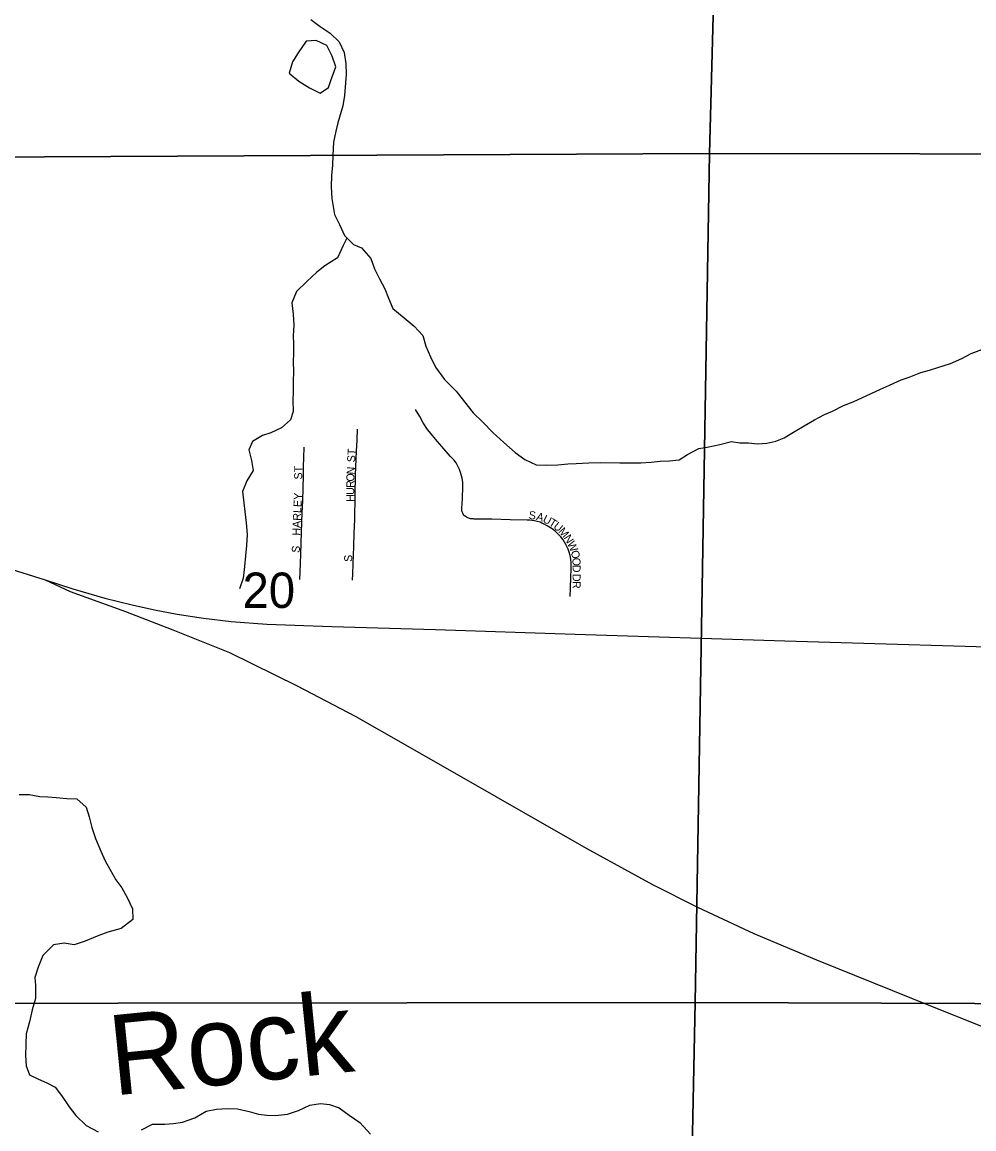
# Model space of a CAD drawing. Extents: x 1772825 to 1773716, y 1138558 to 1139032.
# Drawn here: x 1772828.624 to 1772829.187, y 1138562.068 to 1138562.723 of the extents above; entities that cross this region are included whole.
import ezdxf

# ---------------------------------------------------------------- set-up
doc = ezdxf.new("R2010")
doc.units = 0
for name, color, linetype in [('GM_X_Minor_Lake', 7, 'Continuous'), ('GM_X_Minor_River', 7, 'Continuous'), ('GM_X_Minor_River_Text', 7, 'Continuous'), ('GM_X_Rail_Line', 7, 'Continuous'), ('GM_X_Section', 7, 'Continuous'), ('GM_X_Section_Text', 7, 'Continuous'), ('GM_X_Township_Subdivision', 7, 'Continuous'), ('GM_X_Township_Subdivision_Text', 7, 'Continuous')]:
    doc.layers.add(name, color=color, linetype=linetype)

msp = doc.modelspace()

# ---------------------------------------------------------------- linework, layer by layer
at = {"layer": 'GM_X_Minor_Lake'}
for points in [[(1772828.80638, 1138562.6885), (1772828.8095, 1138562.6967), (1772828.80727, 1138562.70298), (1772828.80409, 1138562.70926), (1772828.79786, 1138562.71215), (1772828.79179, 1138562.7118), (1772828.78721, 1138562.705), (1772828.78376, 1138562.6997), (1772828.78183, 1138562.69288)], [(1772828.78183, 1138562.69288), (1772828.78748, 1138562.6881), (1772828.79389, 1138562.68427), (1772828.80013, 1138562.681), (1772828.80507, 1138562.68439), (1772828.80638, 1138562.6885)]]:
    msp.add_lwpolyline(points, dxfattribs=at)
at = {"layer": 'GM_X_Minor_River'}
for points in [[(1772828.79453, 1138562.7247), (1772828.80018, 1138562.72049), (1772828.80603, 1138562.71666), (1772828.81149, 1138562.7115), (1772828.81429, 1138562.70522), (1772828.81538, 1138562.69838), (1772828.81554, 1138562.69211), (1772828.81451, 1138562.67978), (1772828.81353, 1138562.6735)], [(1772828.81353, 1138562.6735), (1772828.81064, 1138562.66357), (1772828.80946, 1138562.65865), (1772828.80809, 1138562.65202), (1772828.80765, 1138562.64443), (1772828.80742, 1138562.63817), (1772828.80681, 1138562.63248), (1772828.80657, 1138562.62565), (1772828.80709, 1138562.61882), (1772828.80781, 1138562.61407), (1772828.80873, 1138562.60932), (1772828.81153, 1138562.60342), (1772828.81452, 1138562.59675), (1772828.81979, 1138562.59159), (1772828.82471, 1138562.58947), (1772828.83017, 1138562.58316), (1772828.8324, 1138562.57708), (1772828.8352, 1138562.57117), (1772828.83838, 1138562.56527), (1772828.84062, 1138562.55975), (1772828.84323, 1138562.55365), (1772828.84983, 1138562.5481), (1772828.85587, 1138562.54312), (1772828.86095, 1138562.53758), (1772828.8628, 1138562.53131), (1772828.86541, 1138562.52503), (1772828.86841, 1138562.51893), (1772828.87386, 1138562.51168), (1772828.88064, 1138562.5048), (1772828.88552, 1138562.4985), (1772828.89079, 1138562.49182), (1772828.89644, 1138562.48646), (1772828.90247, 1138562.48016), (1772828.90888, 1138562.47442), (1772828.91566, 1138562.46848), (1772828.92132, 1138562.46427), (1772828.92813, 1138562.46118), (1772828.9342, 1138562.46094), (1772828.94084, 1138562.46108), (1772828.94673, 1138562.4618), (1772828.95167, 1138562.46195), (1772828.95926, 1138562.46227), (1772828.9659, 1138562.46241), (1772828.97766, 1138562.46233), (1772828.98999, 1138562.46223), (1772828.99607, 1138562.46276), (1772829.00139, 1138562.46328), (1772829.00708, 1138562.46343), (1772829.01278, 1138562.46415), (1772829.01773, 1138562.46715), (1772829.0244, 1138562.4707), (1772829.02934, 1138562.47161), (1772829.03675, 1138562.47308), (1772829.04378, 1138562.47492), (1772829.04871, 1138562.47413), (1772829.05383, 1138562.47409), (1772829.05914, 1138562.47348), (1772829.06465, 1138562.47401), (1772829.06997, 1138562.4751), (1772829.07491, 1138562.47715), (1772829.08139, 1138562.48109), (1772829.08673, 1138562.48428), (1772829.09283, 1138562.48783), (1772829.09873, 1138562.49083), (1772829.10349, 1138562.49288), (1772829.10996, 1138562.49624), (1772829.11567, 1138562.49848), (1772829.12633, 1138562.50333), (1772829.13186, 1138562.50595), (1772829.13737, 1138562.50818), (1772829.14423, 1138562.51136), (1772829.14898, 1138562.51303), (1772829.15583, 1138562.51582), (1772829.16097, 1138562.51711), (1772829.16591, 1138562.51878), (1772829.17333, 1138562.521), (1772829.18018, 1138562.52399), (1772829.1857, 1138562.52698), (1772829.19198, 1138562.5294)], [(1772828.81602, 1138562.59528), (1772828.81371, 1138562.59088), (1772828.81044, 1138562.58369), (1772828.803, 1138562.57881), (1772828.79823, 1138562.57506), (1772828.79231, 1138562.5696), (1772828.7862, 1138562.56376), (1772828.7833, 1138562.55695), (1772828.7842, 1138562.5503), (1772828.78453, 1138562.54385), (1772828.78411, 1138562.5374), (1772828.78426, 1138562.53266), (1772828.78441, 1138562.52696), (1772828.78419, 1138562.52222), (1772828.78433, 1138562.51615), (1772828.7841, 1138562.51065), (1772828.78425, 1138562.5042), (1772828.78402, 1138562.49945), (1772828.78416, 1138562.49262), (1772828.78261, 1138562.4877), (1772828.77726, 1138562.483), (1772828.77098, 1138562.48001), (1772828.76603, 1138562.47853), (1772828.76013, 1138562.47497), (1772828.75781, 1138562.47005), (1772828.75948, 1138562.46378), (1772828.76038, 1138562.4577), (1772828.75673, 1138562.45165), (1772828.75422, 1138562.44541), (1772828.75493, 1138562.43857), (1772828.75546, 1138562.43345), (1772828.75636, 1138562.4268), (1772828.75688, 1138562.41996), (1772828.75645, 1138562.41333), (1772828.75603, 1138562.40726), (1772828.75542, 1138562.401), (1772828.75461, 1138562.39399), (1772828.75247, 1138562.38774)], [(1772828.62181, 1138562.26596), (1772828.62788, 1138562.2661), (1772828.63414, 1138562.26492), (1772828.63888, 1138562.26469), (1772828.64381, 1138562.26428), (1772828.65006, 1138562.26366), (1772828.65613, 1138562.26342), (1772828.6616, 1138562.25845), (1772828.66327, 1138562.25274), (1772828.66493, 1138562.24647), (1772828.66716, 1138562.24), (1772828.67033, 1138562.23258), (1772828.67275, 1138562.22687), (1772828.67557, 1138562.22191), (1772828.67913, 1138562.21562), (1772828.6827, 1138562.21085), (1772828.68588, 1138562.20514), (1772828.68906, 1138562.19828), (1772828.6892, 1138562.19202), (1772828.68233, 1138562.18676), (1772828.67434, 1138562.18454), (1772828.66807, 1138562.18212), (1772828.66103, 1138562.17933), (1772828.65456, 1138562.1771), (1772828.64849, 1138562.1781), (1772828.64223, 1138562.177), (1772828.63592, 1138562.17079), (1772828.63321, 1138562.16379), (1772828.63127, 1138562.15773), (1772828.63162, 1138562.15299), (1772828.63156, 1138562.14521), (1772828.62961, 1138562.13858), (1772828.62804, 1138562.13157), (1772828.62609, 1138562.12438), (1772828.62586, 1138562.11831), (1772828.62562, 1138562.11167), (1772828.62596, 1138562.1054), (1772828.62801, 1138562.10008), (1772828.6333, 1138562.09757)], [(1772828.6333, 1138562.09757), (1772828.63822, 1138562.09544), (1772828.64332, 1138562.09275), (1772828.64689, 1138562.08798), (1772828.65159, 1138562.08111), (1772828.65553, 1138562.07615), (1772828.66156, 1138562.07022), (1772828.66874, 1138562.06637)], [(1772828.69437, 1138562.06751), (1772828.70084, 1138562.07087), (1772828.70824, 1138562.07101), (1772828.71337, 1138562.07135), (1772828.71869, 1138562.07207), (1772828.72591, 1138562.07467), (1772828.73258, 1138562.07861), (1772828.73885, 1138562.07989), (1772828.74512, 1138562.08022), (1772828.75119, 1138562.07998), (1772828.7582, 1138562.07841), (1772828.76369, 1138562.07685), (1772828.76862, 1138562.07625), (1772828.77374, 1138562.07602), (1772828.78076, 1138562.07691), (1772828.78723, 1138562.07895), (1772828.79408, 1138562.08213), (1772828.80035, 1138562.08322), (1772828.80566, 1138562.08261), (1772828.81134, 1138562.08067), (1772828.81738, 1138562.07626), (1772828.82361, 1138562.07185), (1772828.83001, 1138562.06497)]]:
    msp.add_lwpolyline(points, dxfattribs=at)
at = {"layer": 'GM_X_Rail_Line'}
for points in [[(1772828.43277, 1138562.45322), (1772828.47216, 1138562.4423), (1772828.4962, 1138562.43544), (1772828.52782, 1138562.42662), (1772828.57356, 1138562.41289), (1772828.59734, 1138562.4055), (1772828.63738, 1138562.393)], [(1772828.63738, 1138562.393), (1772828.65209, 1138562.38626), (1772828.68481, 1138562.3743), (1772828.71297, 1138562.36341), (1772828.74642, 1138562.35003), (1772828.78649, 1138562.33043), (1772828.82079, 1138562.3123), (1772828.85074, 1138562.2954), (1772828.95763, 1138562.23428), (1772828.99691, 1138562.21281), (1772829.02352, 1138562.19927), (1772829.05689, 1138562.18379), (1772829.094, 1138562.16818), (1772829.16152, 1138562.141), (1772829.247, 1138562.10689)], [(1772828.63738, 1138562.393), (1772828.65378, 1138562.38775), (1772828.67257, 1138562.3823), (1772828.68877, 1138562.37822), (1772828.70205, 1138562.37537), (1772828.7154, 1138562.37284), (1772828.73114, 1138562.37038), (1772828.74747, 1138562.36844), (1772828.76866, 1138562.36682), (1772828.80708, 1138562.36552), (1772828.86837, 1138562.36358), (1772828.95112, 1138562.36086), (1772829.07526, 1138562.35697), (1772829.23547, 1138562.35214)]]:
    msp.add_lwpolyline(points, dxfattribs=at)
at = {"layer": 'GM_X_Section'}
for points in [[(1772829.53637, 1138563.14606), (1772829.52843, 1138562.6446), (1772829.03068, 1138562.64534), (1772829.04388, 1138563.14186)], [(1772829.03068, 1138562.64534), (1772829.02215, 1138562.14292), (1772828.50962, 1138562.14244), (1772828.51851, 1138562.64277)], [(1772829.52843, 1138562.6446), (1772829.51894, 1138562.14124), (1772829.02215, 1138562.14292), (1772829.03068, 1138562.64534)], [(1772829.02215, 1138562.14292), (1772829.0119, 1138561.63975), (1772828.50281, 1138561.64361), (1772828.50962, 1138562.14244)], [(1772829.51894, 1138562.14124), (1772829.50793, 1138561.63902), (1772829.0119, 1138561.63975), (1772829.02215, 1138562.14292)]]:
    msp.add_lwpolyline(points, close=True, dxfattribs=at)
msp.add_lwpolyline([(1772829.04388, 1138563.14186), (1772829.03068, 1138562.64534), (1772828.51851, 1138562.64277), (1772828.4865, 1138562.67693), (1772828.49871, 1138562.68748), (1772828.50213, 1138562.68878), (1772828.51294, 1138562.68983), (1772828.51768, 1138562.69093), (1772828.52452, 1138562.6924), (1772828.53059, 1138562.69406), (1772828.53571, 1138562.69458), (1772828.53875, 1138562.69513), (1772828.54426, 1138562.69679), (1772828.55661, 1138562.70162), (1772828.56269, 1138562.70423), (1772828.56917, 1138562.70911), (1772828.57528, 1138562.71531), (1772828.5795, 1138562.72153), (1772828.58084, 1138562.72399)], dxfattribs=at)
at = {"layer": 'GM_X_Township_Subdivision'}
for points in [[(1772828.94821, 1138562.38317), (1772828.94835, 1138562.38818), (1772828.94857, 1138562.39467), (1772828.94873, 1138562.39937), (1772828.94873, 1138562.40313), (1772828.94855, 1138562.40534), (1772828.94818, 1138562.40753), (1772828.94767, 1138562.40938), (1772828.94696, 1138562.41114), (1772828.94556, 1138562.41396), (1772828.94397, 1138562.41667), (1772828.94266, 1138562.41847), (1772828.94116, 1138562.42011), (1772828.9393, 1138562.42183), (1772828.93755, 1138562.42318), (1772828.93464, 1138562.42506), (1772828.93241, 1138562.42625), (1772828.93144, 1138562.4267), (1772828.93035, 1138562.4271), (1772828.92865, 1138562.42761), (1772828.9271, 1138562.42795), (1772828.92559, 1138562.42817), (1772828.92426, 1138562.42833), (1772828.92267, 1138562.42843), (1772828.91271, 1138562.42867), (1772828.90173, 1138562.42895), (1772828.89677, 1138562.42902), (1772828.89269, 1138562.42903), (1772828.89142, 1138562.42905), (1772828.89068, 1138562.42908), (1772828.88985, 1138562.42913), (1772828.88917, 1138562.42921), (1772828.88862, 1138562.42931), (1772828.88815, 1138562.42947), (1772828.88751, 1138562.42973), (1772828.88672, 1138562.43017), (1772828.88616, 1138562.43055), (1772828.88554, 1138562.43101), (1772828.88517, 1138562.43142), (1772828.88484, 1138562.43188), (1772828.88454, 1138562.43243), (1772828.88434, 1138562.43287), (1772828.88419, 1138562.43332), (1772828.88404, 1138562.43387), (1772828.88399, 1138562.43426), (1772828.88397, 1138562.43466), (1772828.88403, 1138562.43548), (1772828.88443, 1138562.44098), (1772828.88468, 1138562.44845), (1772828.88456, 1138562.45067), (1772828.88415, 1138562.45316), (1772828.88346, 1138562.4559), (1772828.88266, 1138562.45829), (1772828.88174, 1138562.46032), (1772828.8806, 1138562.46223), (1772828.87929, 1138562.46401), (1772828.87721, 1138562.46635), (1772828.8684, 1138562.47634), (1772828.86581, 1138562.4794), (1772828.86377, 1138562.48211), (1772828.86122, 1138562.48596), (1772828.85907, 1138562.4897), (1772828.85669, 1138562.49386)], [(1772828.81934, 1138562.3928), (1772828.81949, 1138562.39667), (1772828.81972, 1138562.40255), (1772828.82011, 1138562.41277), (1772828.82036, 1138562.42084), (1772828.82059, 1138562.42859), (1772828.82079, 1138562.44317), (1772828.8211, 1138562.45526), (1772828.82173, 1138562.46921), (1772828.822, 1138562.4758), (1772828.82226, 1138562.48228)], [(1772828.78815, 1138562.39331), (1772828.78848, 1138562.40256), (1772828.78869, 1138562.40852), (1772828.78911, 1138562.42137), (1772828.78958, 1138562.43299), (1772828.78982, 1138562.43974), (1772828.79009, 1138562.44746), (1772828.79025, 1138562.45436), (1772828.79037, 1138562.46023), (1772828.79042, 1138562.46521), (1772828.7906, 1138562.47167)]]:
    msp.add_lwpolyline(points, dxfattribs=at)

# ---------------------------------------------------------------- texts
at = {"layer": 'GM_X_Minor_River_Text'}
msp.add_text('Rock', height=0.047368, rotation=5.74851, dxfattribs=at).set_placement((1772828.67763, 1138562.08781))
at = {"layer": 'GM_X_Section_Text'}
msp.add_text('20', height=0.020928, rotation=0.00001, dxfattribs=at).set_placement((1772828.75417, 1138562.37644))
at = {"layer": 'GM_X_Township_Subdivision_Text'}
for s, height, rotation, p in [('ST', 0.004735, 86.42535, (1772828.82077, 1138562.46251)), ('ST', 0.004735, 90, (1772828.78952, 1138562.45245)), ('N', 0.00473, 85.36159, (1772828.82042, 1138562.45527)), ('O', 0.00473, 89.21307, (1772828.82037, 1138562.45118)), ('R', 0.00473, 89.95142, (1772828.82036, 1138562.44745)), ('U', 0.00473, 89.95627, (1772828.82036, 1138562.44329)), ('HARLEY', 0.004735, 87.39923, (1772828.78828, 1138562.41915)), ('H', 0.00473, 89.95627, (1772828.82036, 1138562.43912)), ('S', 0.00473, 352.99017, (1772828.92342, 1138562.42918)), ('A', 0.00473, 344.39985, (1772828.92777, 1138562.42857)), ('U', 0.00473, 332.71171, (1772828.93154, 1138562.42754)), ('T', 0.00473, 328.97065, (1772828.93518, 1138562.42567)), ('U', 0.00473, 319.99853, (1772828.93787, 1138562.42407)), ('M', 0.00473, 311.59724, (1772828.94093, 1138562.42152)), ('N', 0.00473, 302.38068, (1772828.94413, 1138562.41794)), ('S', 0.00473, 83.66247, (1772828.78786, 1138562.4088)), ('W', 0.00473, 294.6777, (1772828.94628, 1138562.41457)), ('S', 0.00473, 90, (1772828.81911, 1138562.4037)), ('O', 0.00473, 284.53446, (1772828.94847, 1138562.40985)), ('O', 0.00473, 272.18581, (1772828.94948, 1138562.40609)), ('D', 0.00473, 270.08745, (1772828.94963, 1138562.40197)), ('D', 0.00473, 269.99284, (1772828.94964, 1138562.39656)), ('R', 0.00473, 269.99405, (1772828.94964, 1138562.39239))]:
    msp.add_text(s, height=height, rotation=rotation, dxfattribs=at).set_placement(p)

doc.saveas('drawing.dxf')
